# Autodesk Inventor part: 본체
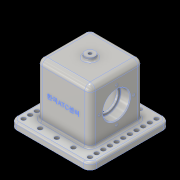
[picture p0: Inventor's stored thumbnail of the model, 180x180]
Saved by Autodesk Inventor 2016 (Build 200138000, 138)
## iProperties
Created: 2018-11
Part Number: 본체
Material: 알루미늄 6061
Document SubType Name: Modeling
Designer: PC-18
Mass: 1036.78 g
Surface Area: 772.355 cm^2
Volume: 383.993 cm^3
Density: 2.7 g/cm^3
Appearance: 알루미늄 - 평지
Author: PC-18
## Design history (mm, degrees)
sketch "스케치1"
  geometry: L1 (60, 60)-(-60, 60); L2 (-60, 60)-(-60, -60); L3 (-60, -60)-(60, -60); L4 (60, -60)-(60, 60); L5 (60, 60)-(-60, -60); L6 (-60, 60)-(60, -60); 1 further point
  constraints: 12 end point, 2 midpoint, 2 parallel, 1 horizontal, 1 perpendicular
  dimensions: "d0" = 120 distance of L3.end L2.end; "d1" = 120 distance of L2.end L1.end
extrude "돌출1" new body sketch "스케치1" distance "d2" = 10; taper "d3" = 0 deg
sketch "스케치2"
  geometry: L1 (40, 40)-(-40, 40); L2 (-40, 40)-(-40, -40); L3 (-40, -40)-(40, -40); L4 (40, -40)-(40, 40); L5 (40, 40)-(-40, -40); L6 (-40, 40)-(40, -40); 1 further point
  constraints: 12 end point, 2 midpoint, 2 parallel, 1 horizontal, 1 perpendicular
  dimensions: "d4" = 80 distance of L3.end L2.end; "d5" = 80 distance of L2.end L1.end
extrude "돌출2" join sketch "스케치2" distance "d6" = 80; taper "d7" = 0 deg
sketch "스케치3"
  geometry: L1 (-23, -30)-(23, -30); L2 (23, -30)-(23, 30); L3 (23, 30)-(-23, 30); L4 (-23, 30)-(-23, -30); L5 (-23, -30)-(23, 30); L6 (23, -30)-(-23, 30); 1 further point
  constraints: 12 end point, 2 midpoint, 2 parallel, 1 horizontal, 1 perpendicular
  dimensions: "d8" = 46 distance of L3.end L2.end; "d9" = 60 distance of L2.end L1.end
extrude "돌출3" cut sketch "스케치3" distance "d10" = 80; taper "d11" = 0 deg
sketch "스케치4"
  geometry: L1 (-10, 100)-(-10, -20) reference; C1 r 20 at (38, 40); 2 further points
  constraints: 1 centre point, 1 horizontal alignment, 1 midpoint
  dimensions: "d12" = 40 diameter of C1; "d13" = 48 distance from line of L1 C1.centre
extrude "돌출4" cut sketch "스케치4" distance "d14" = 14; taper "d15" = 0 deg
hole "구멍1" diameter "d18" = 33; stored, may be unused: countersink angle "d22" = 90 deg, drill point angle "d24" = 118 deg; dims "d16" = 10, "d17" = 10, "d19" = 6, "d20" = 33, "d21" = 2, "d23" = 8
hole "구멍2" diameter "d27" = 40; stored, may be unused: countersink angle "d31" = 90 deg, drill point angle "d33" = 0 deg; dims "d25" = 10, "d26" = 10, "d28" = 6, "d29" = 33, "d30" = 2, "d32" = 14
fillet "모깎기2" dims "d35" = 8
sketch "스케치5"
  geometry: C1 r 7.5 at (0, 0); 1 further point
  constraints: 1 centre point, 1 coincident
  dimensions: "d36" = 15 diameter of C1
extrude "돌출5" join sketch "스케치5" distance "d37" = 5; taper "d38" = 0 deg
hole "구멍3" diameter "d41" = 4.917; stored, may be unused: countersink angle "d45" = 90 deg, drill point angle "d47" = 118 deg; dims "d39" = 10, "d40" = 10, "d42" = 12, "d43" = 33, "d44" = 2, "d46" = 17.1
sketch "스케치6" dims "d48" = 52
  geometry: L1 (-10, 92)-(-10, -28) reference; 3 further points
  constraints: 1 horizontal alignment, 2 other
  dimensions: "d49" = 48 distance from line of L1 point (38, 32)
hole "구멍4" sketch "스케치6" at (64, 32) diameter "d50" = 3.242; stored, may be unused: countersink angle "d54" = 90 deg, drill point angle "d56" = 118 deg; dims "d51" = 8, "d52" = 33, "d53" = 2, "d55" = 10
chamfer "모따기1" distance "d60" = 1; stored, may be unused: second distance "d61" = 2, angle "d62" = 45 deg
fillet "모깎기3" dims "d63" = 0.6
fillet "모깎기4" dims "d64" = 10
fillet "모깎기5" dims "d65" = 3
fillet "모깎기6" dims "d66" = 8
fillet "모깎기7" dims "d67" = 3
hole "구멍5" diameter "d70" = 6.6; stored, may be unused: countersink angle "d74" = 90 deg, drill point angle "d76" = 118 deg; dims "d71" = 8, "d72" = 33, "d73" = 2, "d75" = 10, "d79" = 10, "d80" = 10
sketch "스케치8"
  geometry: C1 r 3.3 at (50, 50) reference; C2 r 3.3 at (50, 40); 10 further points
  constraints: 1 centre point, 1 coincident, 1 vertical alignment
  dimensions: "d81" = 6.6 diameter of C2; "d82" = 10 distance of C1.centre C2.centre; "d83" = 10 distance of point (50, 30) C2.centre; "d84" = 10 distance of point (50, 20) point (50, 30); "d85" = 10 distance of point (50, 10) point (50, 20); "d86" = 10 distance of point (50, 0) point (50, 10); "d87" = 10 distance of point (50, -10) point (50, 0); "d88" = 10 distance of point (50, -20) point (50, -10); "d89" = 10 distance of point (50, -30) point (50, -20); "d90" = 10 distance of point (50, -40) point (50, -30)
hole "구멍6" sketch "스케치8" at (50, 40), (50, 30), (50, 20), (50, 10), (50, 0), (50, -10), (50, -20), (50, -30), (50, -40) diameter "d91" = 6.6; stored, may be unused: countersink angle "d95" = 90 deg, drill point angle "d97" = 118 deg; dims "d92" = 8, "d93" = 33, "d94" = 2, "d96" = 10
sketch "스케치9"
  geometry: C1 r 3.3 at (-50, -40) reference; C2 r 3.3 at (-50, -50); 1 further point
  constraints: 1 centre point
  dimensions: "d101" = 6.6 diameter of C2; "d102" = 10 distance of C1.centre C2.centre
extrude "돌출6" cut sketch "스케치9" stored distance "d103" = 5; taper "d104" = 0 deg
fillet "모깎기8" dims "d105" = 3
node "작업 평면1"
sketch "스케치10" dims "d12" = 40, "d13" = 48
  geometry: L1 (-10.07, -30.398)-(74.07, -30.398); L2 (74.07, -30.398)-(74.07, -37.602); L3 (74.07, -37.602)-(-10.07, -37.602); L4 (-10.07, -37.602)-(-10.07, -30.398); L5 (-18, -82)-(82, -82) reference; 4 further points
  constraints: 3 midpoint, 1 vertical alignment, 2 other
  dimensions: "d107" = 48 distance from line of L5 point (-10.07, -34)
feature "엠보싱1" sketch "스케치10" dims "d8" = 46, "d9" = 60, "d108" = 0.5, "d109" = 0
fillet "모깎기9" dims "d110" = 3
node "솔리드1"
pattern_circular "원형 패턴1" dims angle "d58" = 360 deg
mirror "대칭1"
mirror "대칭2"
pattern_linear "직사각형 패턴1" dims "d100" = 25
mirror "대칭3"
other parameters: "d106" = 12
